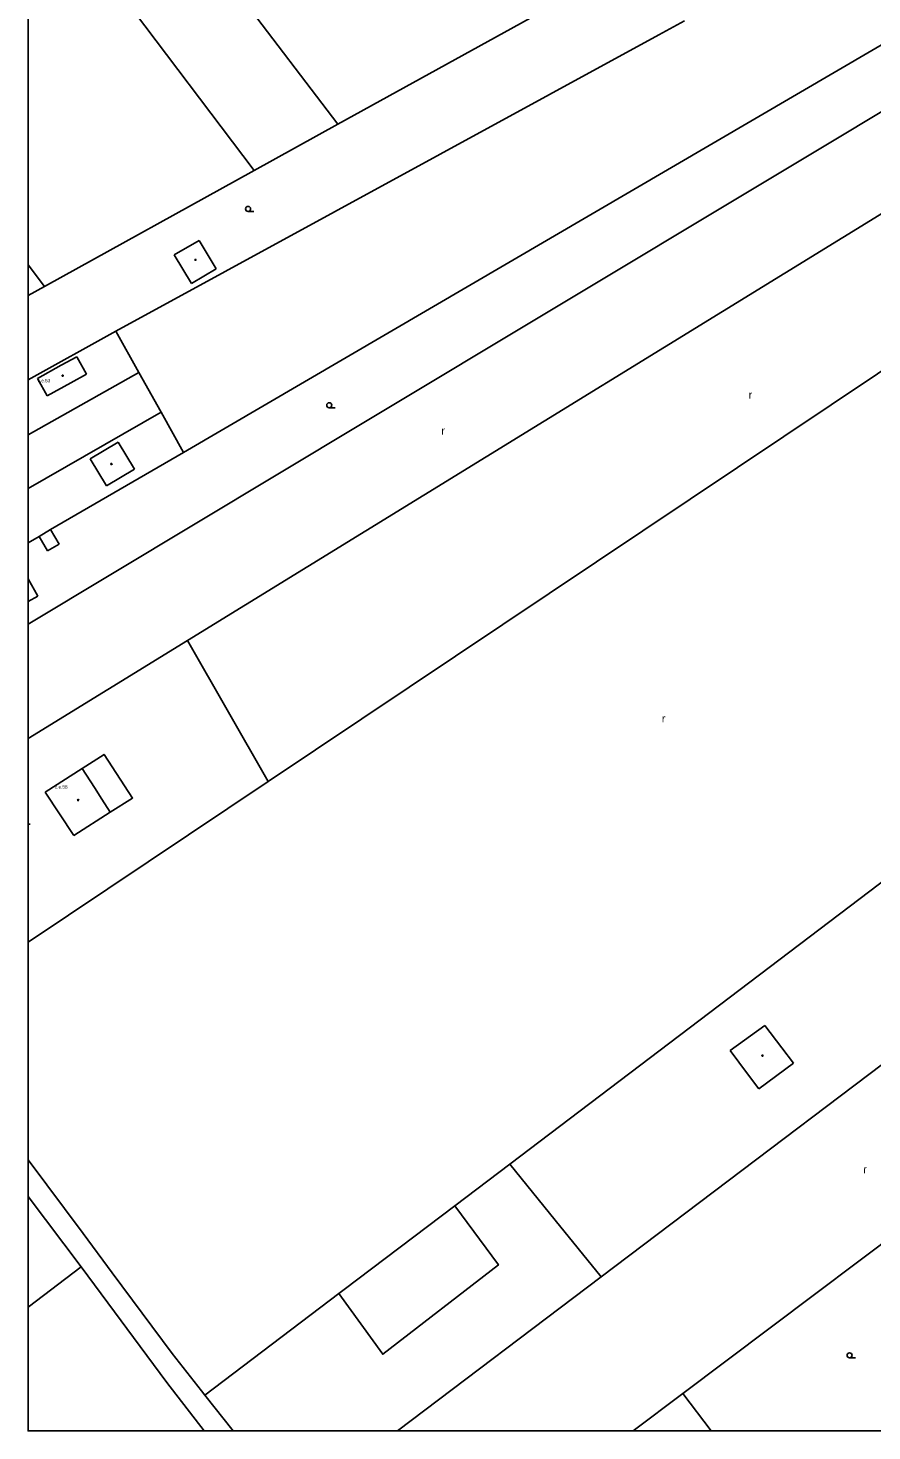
# Model space of a CAD drawing. Extents: x -594386 to -594050, y -1167541 to -1167175.
# Drawn here: x -594386.4 to -594259.8, y -1167540.8 to -1167330.4 of the extents above; entities that cross this region are included whole.
import ezdxf

# ---------------------------------------------------------------- set-up
doc = ezdxf.new("R2010")
doc.units = 0
for name, color, linetype in [('Level 36', 7, 'Continuous'), ('Level 39', 7, 'Continuous'), ('Vrstva 11', 7, 'Continuous'), ('Vrstva 46', 7, 'Continuous'), ('Vrstva 51', 7, 'Continuous'), ('Vrstva 52', 7, 'Continuous'), ('Vrstva 63', 7, 'Continuous'), ('Vrstva 7', 7, 'Continuous')]:
    doc.layers.add(name, color=color, linetype=linetype)

msp = doc.modelspace()

# ---------------------------------------------------------------- linework, layer by layer
at = {"layer": 'Level 36'}
for p, q in [((-594353.37, -1167357.91), (-594352.5, -1167357.91)), ((-594341.19, -1167387.34), (-594340.32, -1167387.34)), ((-594386.36, -1167449.8), (-594386.05, -1167449.8)), ((-594263.16, -1167529.82), (-594262.28, -1167529.82))]:
    msp.add_line(p, q, dxfattribs=at)
for centre in [(-594353.37, -1167357.53), (-594341.19, -1167386.97), (-594263.16, -1167529.45)]:
    msp.add_circle(centre, 0.375, dxfattribs=at)
at = {"layer": 'Level 39'}
for centre, radius in [((-594361.24, -1167365.15), 0.09), ((-594361.24, -1167365.15), 0.0398), ((-594381.18, -1167382.54), 0.09), ((-594381.18, -1167382.54), 0.0398), ((-594373.86, -1167395.77), 0.09), ((-594373.86, -1167395.77), 0.0398), ((-594378.85, -1167446.18), 0.09), ((-594378.85, -1167446.18), 0.0398), ((-594276.23, -1167484.52), 0.09), ((-594276.23, -1167484.52), 0.0398)]:
    msp.add_circle(centre, radius, dxfattribs=at)
at = {"layer": 'Vrstva 11'}
for points in [[(-594374.03, -1167447.98), (-594370.68, -1167445.88), (-594374.96, -1167439.34), (-594378.26, -1167441.43)], [(-594339.74, -1167520.19), (-594333.17, -1167529.3), (-594315.82, -1167515.9), (-594322.36, -1167507.01)]]:
    msp.add_lwpolyline(points, dxfattribs=at)
at = {"layer": 'Vrstva 51'}
for p, q in [((-594386.36, -1167283.71), (-594339.88, -1167344.83)), ((-594352.46, -1167351.78), (-594386.36, -1167306.73)), ((-594386.36, -1167365.91), (-594383.91, -1167369.14)), ((-594386.36, -1167370.49), (-594383.91, -1167369.14)), ((-594386.36, -1167383.16), (-594373.18, -1167375.88)), ((-594386.36, -1167391.42), (-594369.73, -1167382.08)), ((-594386.36, -1167399.45), (-594366.42, -1167388.01)), ((-594386.36, -1167419.81), (-594336.26, -1167389.69)), ((-594386.36, -1167407.6), (-594384.7, -1167406.63)), ((-594386.36, -1167436.94), (-594362.44, -1167422.23)), ((-594350.36, -1167443.4), (-594386.36, -1167467.49)), ((-594386.36, -1167500.12), (-594378.12, -1167511.17)), ((-594378.39, -1167516.2), (-594386.36, -1167505.61)), ((-594386.36, -1167522.21), (-594378.39, -1167516.2)), ((-594330.98, -1167540.79), (-594300.42, -1167517.66)), ((-594359.93, -1167540.79), (-594365.54, -1167533.54)), ((-594359.83, -1167535.42), (-594355.61, -1167540.79)), ((-594288.19, -1167535.19), (-594295.64, -1167540.79)), ((-594283.9, -1167540.79), (-594288.19, -1167535.19))]:
    msp.add_line(p, q, dxfattribs=at)
for points in [[(-594339.88, -1167344.83), (-594308.59, -1167327.56)], [(-594363.06, -1167394.04), (-594252.98, -1167329.77)], [(-594373.18, -1167375.88), (-594291.76, -1167331.42)], [(-594336.26, -1167389.69), (-594247.06, -1167336.19)], [(-594362.44, -1167422.23), (-594237.45, -1167345.36)], [(-594352.46, -1167351.78), (-594339.88, -1167344.83)], [(-594383.91, -1167369.14), (-594352.46, -1167351.78)], [(-594223.76, -1167358.71), (-594350.36, -1167443.4)], [(-594369.73, -1167382.08), (-594373.18, -1167375.88)], [(-594366.42, -1167388.01), (-594369.73, -1167382.08)], [(-594363.06, -1167394.04), (-594366.42, -1167388.01)], [(-594382.97, -1167405.62), (-594363.06, -1167394.04)], [(-594183.77, -1167401.96), (-594314.13, -1167500.77)], [(-594382.97, -1167405.62), (-594384.7, -1167406.63)], [(-594381.71, -1167407.78), (-594382.97, -1167405.62)], [(-594384.7, -1167406.63), (-594383.44, -1167408.79)], [(-594383.44, -1167408.79), (-594381.71, -1167407.78)], [(-594350.36, -1167443.4), (-594362.44, -1167422.23)], [(-594177.93, -1167425.11), (-594300.42, -1167517.66)], [(-594314.13, -1167500.77), (-594322.36, -1167507.01)], [(-594307.31, -1167509.17), (-594314.13, -1167500.77)], [(-594242.05, -1167500.49), (-594288.19, -1167535.19)], [(-594322.36, -1167507.01), (-594338.96, -1167519.6), (-594339.74, -1167520.19)], [(-594300.42, -1167517.66), (-594307.31, -1167509.17)], [(-594378.12, -1167511.17), (-594373.74, -1167517.08)], [(-594365.54, -1167533.54), (-594378.39, -1167516.2)], [(-594373.74, -1167517.08), (-594364.73, -1167529.19)], [(-594339.74, -1167520.19), (-594359.83, -1167535.42)], [(-594364.73, -1167529.19), (-594360.35, -1167534.76)], [(-594360.35, -1167534.76), (-594359.83, -1167535.42)]]:
    msp.add_lwpolyline(points, dxfattribs=at)
at = {"layer": 'Vrstva 52'}
for p, q in [((-594386.36, -1167412.99), (-594384.91, -1167415.58)), ((-594384.91, -1167415.58), (-594386.36, -1167416.4))]:
    msp.add_line(p, q, dxfattribs=at)
for points in [[(-594364.43, -1167364.41), (-594360.71, -1167362.25)], [(-594360.71, -1167362.25), (-594358.17, -1167366.51)], [(-594361.87, -1167368.71), (-594364.43, -1167364.41)], [(-594358.17, -1167366.51), (-594361.87, -1167368.71)], [(-594381.38, -1167380.98), (-594379.07, -1167379.7)], [(-594379.07, -1167379.7), (-594377.61, -1167382.32)], [(-594384.93, -1167382.94), (-594381.38, -1167380.98)], [(-594377.61, -1167382.32), (-594379.93, -1167383.6)], [(-594383.47, -1167385.56), (-594384.93, -1167382.94)], [(-594379.93, -1167383.6), (-594383.47, -1167385.56)], [(-594377.04, -1167395), (-594372.87, -1167392.48)], [(-594372.87, -1167392.48), (-594370.41, -1167396.54)], [(-594374.58, -1167399.07), (-594377.04, -1167395)], [(-594370.41, -1167396.54), (-594374.58, -1167399.07)], [(-594383.8, -1167444.97), (-594378.26, -1167441.43)], [(-594378.26, -1167441.43), (-594376.41, -1167444.28)], [(-594379.5, -1167451.5), (-594383.8, -1167444.97)], [(-594376.41, -1167444.28), (-594375.28, -1167446.05)], [(-594375.28, -1167446.05), (-594374.03, -1167447.98)], [(-594374.03, -1167447.98), (-594379.5, -1167451.5)], [(-594281.07, -1167483.74), (-594275.89, -1167479.97)], [(-594275.89, -1167479.97), (-594273.34, -1167483.33)], [(-594273.34, -1167483.33), (-594271.59, -1167485.62)], [(-594276.75, -1167489.5), (-594278.46, -1167487.22), (-594281.07, -1167483.74)], [(-594271.59, -1167485.62), (-594276.75, -1167489.5)]]:
    msp.add_lwpolyline(points, dxfattribs=at)
at = {"layer": 'Vrstva 63'}
msp.add_lwpolyline([(-594386.36, -1167175.43), (-594049.75, -1167175.43), (-594049.75, -1167540.79), (-594386.36, -1167540.79)], close=True, dxfattribs=at)
at = {"layer": 'Vrstva 7'}
msp.add_lwpolyline([(-594287.9, -1167329.33), (-594291.76, -1167331.42)], dxfattribs=at)

# ---------------------------------------------------------------- texts
at = {"layer": 'Level 36'}
for p in [(-594278.29, -1167386), (-594324.37, -1167391.38), (-594291.32, -1167434.54), (-594261.12, -1167502.17)]:
    msp.add_text('r', height=1.2, dxfattribs=at).set_placement(p)
at = {"layer": 'Vrstva 46'}
for s, p in [('c.e.53', (-594384.91, -1167383.52)), ('c.e.58', (-594382.32, -1167444.45))]:
    msp.add_text(s, height=0.5, dxfattribs=at).set_placement(p)

doc.saveas('drawing.dxf')
